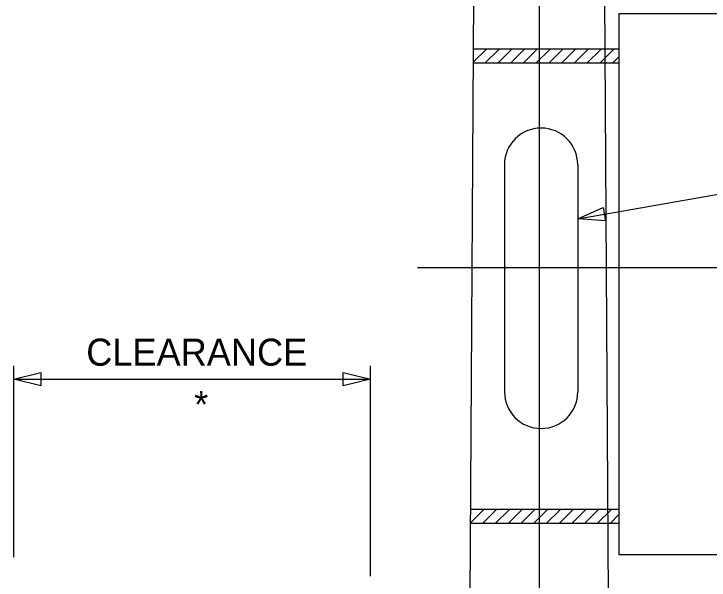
# Model space of a CAD drawing. Extents: x 1299104.7 to 1299141.5, y 239689.9 to 239711.9.
# Drawn here: x 1299109.286 to 1299112.372, y 239698.469 to 239700.983 of the extents above; entities that cross this region are included whole.
import ezdxf

# ---------------------------------------------------------------- set-up
doc = ezdxf.new("R2010")
doc.units = 0
for name, color, linetype in [('DIM TXT', 7, 'Continuous'), ('Level 3', 7, 'Continuous'), ('Level 7', 7, 'Continuous'), ('Level 8', 7, 'Continuous')]:
    doc.layers.add(name, color=color, linetype=linetype)

msp = doc.modelspace()

# ---------------------------------------------------------------- linework, layer by layer
at = {"layer": 'Level 3'}
for p, q in [((1299111.3057, 239697.3558), (1299111.3303, 239701.4808)), ((1299111.9307, 239697.3558), (1299111.9062, 239701.4808)), ((1299111.326, 239700.7695), (1299111.383, 239700.8264)), ((1299111.9717, 239700.8264), (1299111.3264, 239700.8264)), ((1299111.3264, 239700.8264), (1299111.3264, 239700.8264)), ((1299111.377, 239700.7639), (1299111.4395, 239700.8264)), ((1299111.4336, 239700.7639), (1299111.4961, 239700.8264)), ((1299111.4902, 239700.7639), (1299111.5527, 239700.8264)), ((1299111.5467, 239700.7639), (1299111.6092, 239700.8264)), ((1299111.6033, 239700.7639), (1299111.6658, 239700.8264)), ((1299111.6599, 239700.7639), (1299111.7224, 239700.8264)), ((1299111.7164, 239700.7639), (1299111.7789, 239700.8264)), ((1299111.773, 239700.7639), (1299111.8355, 239700.8264)), ((1299111.8296, 239700.7639), (1299111.8921, 239700.8264)), ((1299111.8861, 239700.7639), (1299111.9486, 239700.8264)), ((1299111.9427, 239700.7639), (1299111.9717, 239700.7929)), ((1299111.9717, 239700.7639), (1299111.326, 239700.7639)), ((1299111.4632, 239700.3133), (1299111.4635, 239699.3053)), ((1299111.7886, 239700.3134), (1299111.7889, 239699.3053)), ((1299111.3153, 239698.726), (1299111.3722, 239698.783)), ((1299111.9717, 239698.783), (1299111.3156, 239698.783)), ((1299111.3156, 239698.783), (1299111.3156, 239698.783)), ((1299111.3663, 239698.7205), (1299111.4288, 239698.783)), ((1299111.4228, 239698.7205), (1299111.4853, 239698.783)), ((1299111.4794, 239698.7205), (1299111.5419, 239698.783)), ((1299111.536, 239698.7205), (1299111.5985, 239698.783)), ((1299111.5925, 239698.7205), (1299111.655, 239698.783)), ((1299111.6491, 239698.7205), (1299111.7116, 239698.783)), ((1299111.7057, 239698.7205), (1299111.7682, 239698.783)), ((1299111.7622, 239698.7205), (1299111.8247, 239698.783)), ((1299111.8188, 239698.7205), (1299111.8813, 239698.783)), ((1299111.8754, 239698.7205), (1299111.9379, 239698.783)), ((1299111.9319, 239698.7205), (1299111.9717, 239698.7602)), ((1299111.9717, 239698.7205), (1299111.3153, 239698.7205))]:
    msp.add_line(p, q, dxfattribs=at)
msp.add_lwpolyline([(1299111.9717, 239698.5827), (1299112.8552, 239698.5827), (1299112.8552, 239700.9827), (1299111.9717, 239700.9827)], close=True, dxfattribs=at)
for centre, start, end in [((1299111.6259, 239700.3133), 0, 180), ((1299111.6262, 239699.3053), 180, 0)]:
    msp.add_arc(centre, 0.1627, start, end, dxfattribs=at)
at = {"layer": 'Level 7'}
for p, q in [((1299111.6182, 239710.05), (1299111.6182, 239696.1358)), ((1299111.0775, 239699.8577), (1299114.0486, 239699.8577))]:
    msp.add_line(p, q, dxfattribs=at)
at = {"layer": 'Level 8'}
for p, q in [((1299111.7887, 239700.0736), (1299113.6584, 239700.4003)), ((1299109.2861, 239698.571), (1299109.2861, 239699.4211)), ((1299110.8682, 239698.4862), (1299110.8682, 239699.4211)), ((1299109.2861, 239699.3611), (1299110.8682, 239699.3611))]:
    msp.add_line(p, q, dxfattribs=at)
for points in [[(1299111.912, 239700.0647), (1299111.7887, 239700.0736), (1299111.9017, 239700.1238)], [(1299109.4061, 239699.3311), (1299109.2861, 239699.3611), (1299109.4061, 239699.3911)], [(1299110.7482, 239699.3911), (1299110.8682, 239699.3611), (1299110.7482, 239699.3311)]]:
    msp.add_lwpolyline(points, close=True, dxfattribs=at)

# ---------------------------------------------------------------- texts
at = {"layer": 'DIM TXT'}
for s, p in [('CLEARANCE', (1299109.6072, 239699.4211)), ('*', (1299110.0864, 239699.1894))]:
    msp.add_text(s, height=0.12, dxfattribs=at).set_placement(p)

doc.saveas('drawing.dxf')
